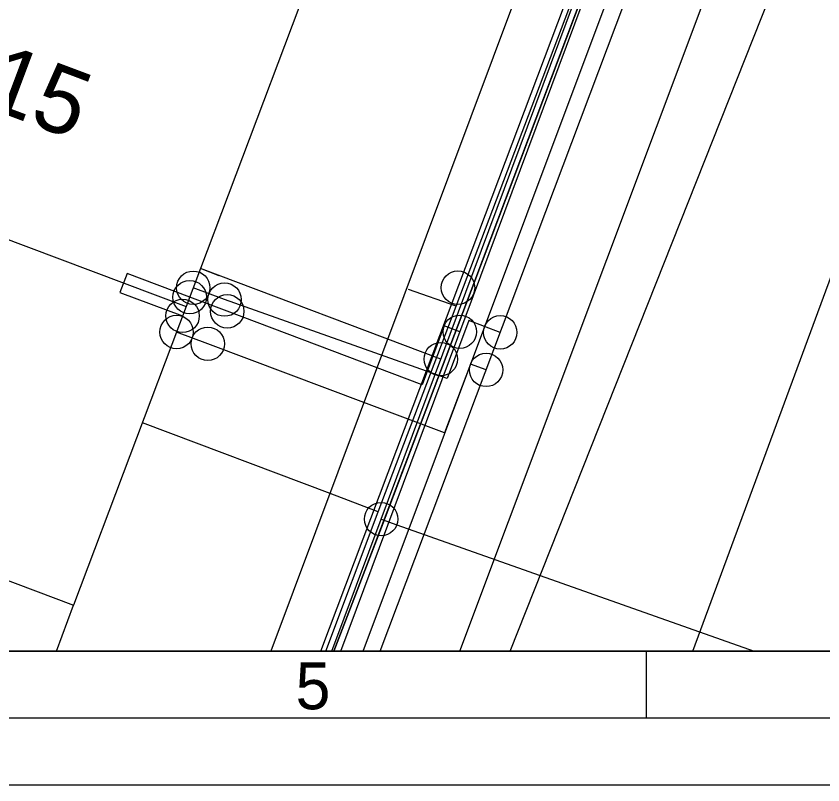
# Model space of a CAD drawing. Extents: x 192672 to 192910, y 446344 to 446512.
# Drawn here: x 192711.22 to 192723.28, y 446343.56 to 446355.04 of the extents above; entities that cross this region are included whole.
import ezdxf

# ---------------------------------------------------------------- set-up
doc = ezdxf.new("R2010")
doc.units = 0
for name, color, linetype in [('1010 viewport', 7, 'Continuous'), ('B-OI-KL-()_MANTELBUIS_WATER-G', 7, 'Continuous'), ('B-OI-KL-()_PUNTVANLEVERING_WATER-S', 7, 'Continuous'), ('B-OI-KL-BUISLEIDING_OLIEGASCHEMICALIEN_GASLAGEDRUK-G', 7, 'Continuous'), ('B-OI-KL-DATA-G', 7, 'Continuous'), ('B-OI-KL-DATA_KABELBED-G', 7, 'Continuous'), ('B-OI-KL-DATA_MOF-S', 7, 'Continuous'), ('B-OI-KL-ET_LS-G', 7, 'Continuous'), ('B-OI-KL-ET_LS_DELIVERYPOINT-S', 7, 'Continuous'), ('B-OI-KL-ET_LS_MOF-S', 7, 'Continuous'), ('B-OI-KL-GAS_LD_AFTAKZADEL-S', 7, 'Continuous'), ('B-OI-KL-GAS_LD_DELIVERYPOINT-S', 7, 'Continuous'), ('B-OI-KL-GAS_LD_OVERGANGSSTUK-S', 7, 'Continuous'), ('B-OI-KL-WATER-G', 7, 'Continuous'), ('B-OI-RI-RIOOLVRIJVERVAL-G', 7, 'Continuous'), ('Default', 7, 'Continuous'), ('huisnummerreeks BGT', 7, 'Continuous'), ('kant open verharding', 7, 'Continuous'), ('kant verharding', 7, 'Continuous'), ('pand op maaiveld vlak', 7, 'Continuous'), ('X-XX-AL-TEKENBLAD-S', 7, 'Continuous')]:
    doc.layers.add(name, color=color, linetype=linetype)

# ---------------------------------------------------------------- blocks, each defined once
blk = doc.blocks.new('B-OI-KL-GAS_LD_AFTAKZADEL-S')
at = {"layer": 'Default'}
blk.add_circle((0, 0), 0.25, dxfattribs=at)
blk = doc.blocks.new('B-OI-KL-GAS_LD_DELIVERYPOINT-S')
at = {"layer": 'Default'}
blk.add_circle((0, 0), 0.25, dxfattribs=at)
blk = doc.blocks.new('B-OI-KL-GAS_LD_OVERGANGSSTUK-S')
at = {"layer": 'Default'}
blk.add_circle((0, 0), 0.25, dxfattribs=at)
blk = doc.blocks.new('B-OI-KL-ET_LS_DELIVERYPOINT-S')
at = {"layer": 'Default'}
blk.add_circle((0, 0), 0.25, dxfattribs=at)
blk = doc.blocks.new('B-OI-KL-ET_LS_MOF-S')
at = {"layer": 'Default'}
blk.add_circle((0, 0), 0.25, dxfattribs=at)
blk = doc.blocks.new('B-OI-KL-()_PUNTVANLEVERING_WATER-S')
at = {"layer": 'Default'}
blk.add_circle((0, 0), 0.25, dxfattribs=at)
blk = doc.blocks.new('B-OI-KL-DATA_MOF-S')
at = {"layer": 'Default'}
blk.add_circle((0, 0), 0.25, dxfattribs=at)

msp = doc.modelspace()

# ---------------------------------------------------------------- linework, layer by layer
at = {"layer": '1010 viewport'}
msp.add_lwpolyline([(192675.743, 446509.756), (192860.643, 446509.756), (192860.643, 446345.556), (192675.743, 446345.556)], close=True, dxfattribs=at)
at = {"layer": 'B-OI-KL-()_MANTELBUIS_WATER-G'}
msp.add_lwpolyline([(192714.258, 446351.164), (192713.977, 446351.27)], dxfattribs=at)
at = {"layer": 'B-OI-KL-BUISLEIDING_OLIEGASCHEMICALIEN_GASLAGEDRUK-G'}
for points in [[(192716.663, 446345.556), (192724.878, 446367.369), (192730.944, 446383.739), (192732.424, 446387.662), (192733.825, 446391.479)], [(192714.338, 446350.807), (192713.87, 446350.984)], [(192718.456, 446350.317), (192717.989, 446350.496), (192717.663, 446349.63), (192714.338, 446350.807)], [(192714.087, 446350.146), (192713.621, 446350.322)], [(192718.245, 446349.756), (192718.011, 446349.844), (192717.623, 446348.814), (192714.087, 446350.146)]]:
    msp.add_lwpolyline(points, dxfattribs=at)
at = {"layer": 'B-OI-KL-DATA-G'}
msp.add_line((192715.85, 446345.556), (192716.633, 446347.634), dxfattribs=at)
for points in [[(192768.74, 446486.807), (192749.794, 446435.599), (192742.072, 446415.039), (192739.06, 446406.841), (192738.917, 446406.249), (192738.75, 446405.758), (192738.438, 446405.088), (192738.002, 446404.406), (192737.543, 446403.858), (192737.067, 446403.408), (192736.56, 446403.025), (192736.06, 446402.723), (192733.684, 446396.245), (192734.518, 446394.712), (192730.316, 446383.423), (192727.316, 446375.697), (192722.899, 446364.033), (192722.458, 446362.715), (192718.077, 446351.086), (192716.68, 446347.404), (192715.968, 446345.556)], [(192768.74, 446486.807), (192749.794, 446435.599), (192742.072, 446415.039), (192739.06, 446406.841), (192738.917, 446406.249), (192738.75, 446405.758), (192738.438, 446405.088), (192738.002, 446404.406), (192737.543, 446403.858), (192737.067, 446403.408), (192736.56, 446403.025), (192736.06, 446402.723), (192733.684, 446396.245), (192734.518, 446394.712), (192730.316, 446383.423), (192727.316, 446375.697), (192722.899, 446364.033), (192722.458, 446362.715), (192718.077, 446351.086), (192716.68, 446347.404), (192715.968, 446345.556)], [(192768.74, 446486.807), (192749.794, 446435.599), (192742.072, 446415.039), (192739.06, 446406.841), (192738.917, 446406.249), (192738.75, 446405.758), (192738.438, 446405.088), (192738.002, 446404.406), (192737.543, 446403.858), (192737.067, 446403.408), (192736.56, 446403.025), (192736.06, 446402.723), (192733.684, 446396.245), (192734.518, 446394.712), (192730.316, 446383.423), (192727.316, 446375.697), (192722.899, 446364.033), (192722.458, 446362.715), (192718.077, 446351.086), (192716.68, 446347.404), (192715.968, 446345.556)], [(192768.74, 446486.807), (192749.794, 446435.599), (192742.072, 446415.039), (192739.06, 446406.841), (192738.917, 446406.249), (192738.75, 446405.758), (192738.438, 446405.088), (192738.002, 446404.406), (192737.543, 446403.858), (192737.067, 446403.408), (192736.56, 446403.025), (192736.06, 446402.723), (192733.684, 446396.245), (192734.518, 446394.712), (192730.316, 446383.423), (192727.316, 446375.697), (192722.899, 446364.033), (192722.458, 446362.715), (192718.077, 446351.086), (192716.68, 446347.404), (192715.968, 446345.556)], [(192768.74, 446486.807), (192749.794, 446435.599), (192742.072, 446415.039), (192739.06, 446406.841), (192738.917, 446406.249), (192738.75, 446405.758), (192738.438, 446405.088), (192738.002, 446404.406), (192737.543, 446403.858), (192737.067, 446403.408), (192736.56, 446403.025), (192736.06, 446402.723), (192733.684, 446396.245), (192734.518, 446394.712), (192730.316, 446383.423), (192727.316, 446375.697), (192722.899, 446364.033), (192722.458, 446362.715), (192718.077, 446351.086), (192716.68, 446347.404), (192715.968, 446345.556)], [(192768.74, 446486.807), (192749.794, 446435.599), (192742.072, 446415.039), (192739.06, 446406.841), (192738.917, 446406.249), (192738.75, 446405.758), (192738.438, 446405.088), (192738.002, 446404.406), (192737.543, 446403.858), (192737.067, 446403.408), (192736.56, 446403.025), (192736.06, 446402.723), (192733.684, 446396.245), (192734.518, 446394.712), (192730.316, 446383.423), (192727.316, 446375.697), (192722.899, 446364.033), (192722.458, 446362.715), (192718.077, 446351.086), (192716.68, 446347.404), (192715.968, 446345.556)], [(192768.74, 446486.807), (192749.794, 446435.599), (192742.072, 446415.039), (192739.06, 446406.841), (192738.917, 446406.249), (192738.75, 446405.758), (192738.438, 446405.088), (192738.002, 446404.406), (192737.543, 446403.858), (192737.067, 446403.408), (192736.56, 446403.025), (192736.06, 446402.723), (192733.684, 446396.245), (192734.518, 446394.712), (192730.316, 446383.423), (192727.316, 446375.697), (192722.899, 446364.033), (192722.458, 446362.715), (192718.077, 446351.086), (192716.68, 446347.404), (192715.968, 446345.556)], [(192768.74, 446486.807), (192749.794, 446435.599), (192742.072, 446415.039), (192739.06, 446406.841), (192738.917, 446406.249), (192738.75, 446405.758), (192738.438, 446405.088), (192738.002, 446404.406), (192737.543, 446403.858), (192737.067, 446403.408), (192736.56, 446403.025), (192736.06, 446402.723), (192733.684, 446396.245), (192734.518, 446394.712), (192730.316, 446383.423), (192727.316, 446375.697), (192722.899, 446364.033), (192722.458, 446362.715), (192718.077, 446351.086), (192716.68, 446347.404), (192715.968, 446345.556)], [(192768.74, 446486.807), (192749.794, 446435.599), (192742.072, 446415.039), (192739.06, 446406.841), (192738.917, 446406.249), (192738.75, 446405.758), (192738.438, 446405.088), (192738.002, 446404.406), (192737.543, 446403.858), (192737.067, 446403.408), (192736.56, 446403.025), (192736.06, 446402.723), (192733.684, 446396.245), (192734.518, 446394.712), (192730.316, 446383.423), (192727.316, 446375.697), (192722.899, 446364.033), (192722.458, 446362.715), (192718.077, 446351.086), (192716.68, 446347.404), (192715.968, 446345.556)], [(192768.74, 446486.807), (192749.794, 446435.599), (192742.072, 446415.039), (192739.06, 446406.841), (192738.917, 446406.249), (192738.75, 446405.758), (192738.438, 446405.088), (192738.002, 446404.406), (192737.543, 446403.858), (192737.067, 446403.408), (192736.56, 446403.025), (192736.06, 446402.723), (192733.684, 446396.245), (192734.518, 446394.712), (192730.316, 446383.423), (192727.316, 446375.697), (192722.899, 446364.033), (192722.458, 446362.715), (192718.077, 446351.086), (192716.68, 446347.404), (192715.968, 446345.556)], [(192768.74, 446486.807), (192749.794, 446435.599), (192742.072, 446415.039), (192739.06, 446406.841), (192738.917, 446406.249), (192738.75, 446405.758), (192738.438, 446405.088), (192738.002, 446404.406), (192737.543, 446403.858), (192737.067, 446403.408), (192736.56, 446403.025), (192736.06, 446402.723), (192733.684, 446396.245), (192734.518, 446394.712), (192730.316, 446383.423), (192727.316, 446375.697), (192722.899, 446364.033), (192722.458, 446362.715), (192718.077, 446351.086), (192716.68, 446347.404), (192715.968, 446345.556)], [(192768.74, 446486.807), (192749.794, 446435.599), (192742.072, 446415.039), (192739.06, 446406.841), (192738.917, 446406.249), (192738.75, 446405.758), (192738.438, 446405.088), (192738.002, 446404.406), (192737.543, 446403.858), (192737.067, 446403.408), (192736.56, 446403.025), (192736.06, 446402.723), (192733.684, 446396.245), (192734.518, 446394.712), (192730.316, 446383.423), (192727.316, 446375.697), (192722.899, 446364.033), (192722.458, 446362.715), (192718.077, 446351.086), (192716.68, 446347.404), (192715.968, 446345.556)], [(192768.74, 446486.807), (192749.794, 446435.599), (192742.072, 446415.039), (192739.06, 446406.841), (192738.917, 446406.249), (192738.75, 446405.758), (192738.438, 446405.088), (192738.002, 446404.406), (192737.543, 446403.858), (192737.067, 446403.408), (192736.56, 446403.025), (192736.06, 446402.723), (192733.684, 446396.245), (192734.518, 446394.712), (192730.316, 446383.423), (192727.316, 446375.697), (192722.899, 446364.033), (192722.458, 446362.715), (192718.077, 446351.086), (192716.68, 446347.404), (192715.968, 446345.556)], [(192768.74, 446486.807), (192749.794, 446435.599), (192742.072, 446415.039), (192739.06, 446406.841), (192738.917, 446406.249), (192738.75, 446405.758), (192738.438, 446405.088), (192738.002, 446404.406), (192737.543, 446403.858), (192737.067, 446403.408), (192736.56, 446403.025), (192736.06, 446402.723), (192733.684, 446396.245), (192734.518, 446394.712), (192730.316, 446383.423), (192727.316, 446375.697), (192722.899, 446364.033), (192722.458, 446362.715), (192718.077, 446351.086), (192716.68, 446347.404), (192715.968, 446345.556)], [(192768.74, 446486.807), (192749.794, 446435.599), (192742.072, 446415.039), (192739.06, 446406.841), (192738.917, 446406.249), (192738.75, 446405.758), (192738.438, 446405.088), (192738.002, 446404.406), (192737.543, 446403.858), (192737.067, 446403.408), (192736.56, 446403.025), (192736.06, 446402.723), (192733.684, 446396.245), (192734.518, 446394.712), (192730.316, 446383.423), (192727.316, 446375.697), (192722.899, 446364.033), (192722.458, 446362.715), (192718.077, 446351.086), (192716.68, 446347.404), (192715.968, 446345.556)], [(192675.743, 446430.156), (192678.122, 446429.261), (192683.193, 446427.673), (192696.077, 446422.823), (192719.012, 446414.118), (192720.2, 446413.77), (192739.06, 446406.841), (192738.917, 446406.249), (192738.75, 446405.758), (192738.438, 446405.088), (192738.002, 446404.406), (192737.543, 446403.858), (192737.067, 446403.408), (192736.56, 446403.025), (192736.06, 446402.723), (192733.684, 446396.245), (192734.518, 446394.712), (192730.316, 446383.423), (192727.316, 446375.697), (192722.899, 446364.033), (192722.458, 446362.715), (192718.077, 446351.086), (192716.68, 446347.404), (192715.968, 446345.556)], [(192675.743, 446430.156), (192678.122, 446429.261), (192683.193, 446427.673), (192696.077, 446422.823), (192719.012, 446414.118), (192720.2, 446413.77), (192739.06, 446406.841), (192738.917, 446406.249), (192738.75, 446405.758), (192738.438, 446405.088), (192738.002, 446404.406), (192737.543, 446403.858), (192737.067, 446403.408), (192736.56, 446403.025), (192736.06, 446402.723), (192733.684, 446396.245), (192734.518, 446394.712), (192730.316, 446383.423), (192727.316, 446375.697), (192722.899, 446364.033), (192722.458, 446362.715), (192718.077, 446351.086), (192716.68, 446347.404), (192715.968, 446345.556)], [(192675.743, 446430.156), (192678.122, 446429.261), (192683.193, 446427.673), (192696.077, 446422.823), (192719.012, 446414.118), (192720.2, 446413.77), (192739.06, 446406.841), (192738.917, 446406.249), (192738.75, 446405.758), (192738.438, 446405.088), (192738.002, 446404.406), (192737.543, 446403.858), (192737.067, 446403.408), (192736.56, 446403.025), (192736.06, 446402.723), (192733.684, 446396.245), (192734.518, 446394.712), (192730.316, 446383.423), (192727.316, 446375.697), (192722.899, 446364.033), (192722.458, 446362.715), (192718.077, 446351.086), (192716.68, 446347.404), (192715.968, 446345.556)], [(192675.743, 446430.156), (192678.122, 446429.261), (192683.193, 446427.673), (192696.077, 446422.823), (192719.012, 446414.118), (192720.2, 446413.77), (192739.06, 446406.841), (192738.917, 446406.249), (192738.75, 446405.758), (192738.438, 446405.088), (192738.002, 446404.406), (192737.543, 446403.858), (192737.067, 446403.408), (192736.56, 446403.025), (192736.06, 446402.723), (192733.684, 446396.245), (192734.518, 446394.712), (192730.316, 446383.423), (192727.316, 446375.697), (192722.899, 446364.033), (192722.458, 446362.715), (192718.077, 446351.086), (192716.68, 446347.404), (192715.968, 446345.556)], [(192675.743, 446430.156), (192678.122, 446429.261), (192683.193, 446427.673), (192696.077, 446422.823), (192719.012, 446414.118), (192720.2, 446413.77), (192739.06, 446406.841), (192738.917, 446406.249), (192738.75, 446405.758), (192738.438, 446405.088), (192738.002, 446404.406), (192737.543, 446403.858), (192737.067, 446403.408), (192736.56, 446403.025), (192736.06, 446402.723), (192733.684, 446396.245), (192734.518, 446394.712), (192730.316, 446383.423), (192727.316, 446375.697), (192722.899, 446364.033), (192722.458, 446362.715), (192718.077, 446351.086), (192716.68, 446347.404), (192715.968, 446345.556)], [(192675.743, 446430.156), (192678.122, 446429.261), (192683.193, 446427.673), (192696.077, 446422.823), (192719.012, 446414.118), (192720.2, 446413.77), (192739.06, 446406.841), (192738.917, 446406.249), (192738.75, 446405.758), (192738.438, 446405.088), (192738.002, 446404.406), (192737.543, 446403.858), (192737.067, 446403.408), (192736.56, 446403.025), (192736.06, 446402.723), (192733.684, 446396.245), (192734.518, 446394.712), (192730.316, 446383.423), (192727.316, 446375.697), (192722.899, 446364.033), (192722.458, 446362.715), (192718.077, 446351.086), (192716.68, 446347.404), (192715.968, 446345.556)], [(192715.968, 446345.556), (192716.68, 446347.404), (192718.077, 446351.086), (192722.458, 446362.715), (192722.899, 446364.033), (192727.316, 446375.697), (192730.316, 446383.423), (192734.518, 446394.712), (192733.684, 446396.245), (192736.06, 446402.723), (192736.56, 446403.025), (192737.067, 446403.408), (192737.543, 446403.858), (192738.002, 446404.406), (192738.438, 446405.088), (192738.75, 446405.758), (192738.917, 446406.249), (192739.06, 446406.841), (192720.2, 446413.77), (192719.012, 446414.118), (192698.154, 446422.035)], [(192715.968, 446345.556), (192716.68, 446347.404), (192718.077, 446351.086), (192722.458, 446362.715), (192722.899, 446364.033), (192727.316, 446375.697), (192730.316, 446383.423), (192734.518, 446394.712), (192733.684, 446396.245), (192736.06, 446402.723), (192736.56, 446403.025), (192737.067, 446403.408), (192737.543, 446403.858), (192738.002, 446404.406), (192738.438, 446405.088), (192738.75, 446405.758), (192738.917, 446406.249), (192739.06, 446406.841), (192720.2, 446413.77), (192719.012, 446414.118), (192703.056, 446420.174)], [(192715.968, 446345.556), (192716.68, 446347.404), (192718.077, 446351.086), (192722.458, 446362.715), (192722.899, 446364.033), (192727.316, 446375.697), (192730.316, 446383.423), (192734.518, 446394.712), (192733.684, 446396.245), (192736.06, 446402.723), (192736.56, 446403.025), (192737.067, 446403.408), (192737.543, 446403.858), (192738.002, 446404.406), (192738.438, 446405.088), (192738.75, 446405.758), (192738.917, 446406.249), (192739.06, 446406.841), (192720.2, 446413.77), (192719.012, 446414.118), (192707.704, 446418.41)], [(192733.785, 446392.743), (192730.316, 446383.423), (192727.316, 446375.697), (192722.899, 446364.033), (192722.458, 446362.715), (192718.077, 446351.086), (192716.68, 446347.404), (192715.968, 446345.556)], [(192718.113, 446380.217), (192718.126, 446380.244), (192727.316, 446375.697), (192722.899, 446364.033), (192722.458, 446362.715), (192718.077, 446351.086), (192716.68, 446347.404), (192715.968, 446345.556)], [(192718.113, 446380.217), (192718.126, 446380.244), (192727.316, 446375.697), (192722.899, 446364.033), (192722.458, 446362.715), (192718.077, 446351.086), (192716.68, 446347.404), (192715.968, 446345.556)], [(192718.113, 446380.217), (192718.126, 446380.244), (192727.316, 446375.697), (192722.899, 446364.033), (192722.458, 446362.715), (192718.077, 446351.086), (192716.68, 446347.404), (192715.968, 446345.556)], [(192718.113, 446380.217), (192718.126, 446380.244), (192727.316, 446375.697), (192722.899, 446364.033), (192722.458, 446362.715), (192718.077, 446351.086), (192716.68, 446347.404), (192715.968, 446345.556)], [(192718.113, 446380.217), (192718.126, 446380.244), (192727.316, 446375.697), (192722.899, 446364.033), (192722.458, 446362.715), (192718.077, 446351.086), (192716.68, 446347.404), (192715.968, 446345.556)], [(192718.113, 446380.217), (192718.126, 446380.244), (192727.316, 446375.697), (192722.899, 446364.033), (192722.458, 446362.715), (192718.077, 446351.086), (192716.68, 446347.404), (192715.968, 446345.556)], [(192718.113, 446380.217), (192718.126, 446380.244), (192727.316, 446375.697), (192722.899, 446364.033), (192722.458, 446362.715), (192718.077, 446351.086), (192716.68, 446347.404), (192715.968, 446345.556)], [(192718.113, 446380.217), (192718.126, 446380.244), (192727.316, 446375.697), (192722.899, 446364.033), (192722.458, 446362.715), (192718.077, 446351.086), (192716.68, 446347.404), (192716.398, 446346.672)], [(192718.113, 446380.217), (192718.126, 446380.244), (192727.316, 446375.697), (192722.899, 446364.033), (192722.458, 446362.715), (192718.202, 446351.418)], [(192717.8, 446350.711), (192719.809, 446356.02)], [(192717.8, 446350.711), (192717.084, 446350.956)], [(192716.633, 446347.634), (192717.8, 446350.711)], [(192716.633, 446347.634), (192715.917, 446347.909), (192713.11, 446348.966)]]:
    msp.add_lwpolyline(points, dxfattribs=at)
at = {"layer": 'B-OI-KL-DATA_KABELBED-G'}
msp.add_line((192716.398, 446346.672), (192715.968, 446345.556), dxfattribs=at)
for points in [[(192715.778, 446345.556), (192717.157, 446349.216), (192720.197, 446357.284), (192722.27, 446362.784), (192722.711, 446364.103), (192724.092, 446367.75), (192725.922, 446372.585), (192725.924, 446372.588), (192726.95, 446375.299), (192730.073, 446383.511), (192734.61, 446395.441)], [(192720.004, 446356.201), (192718.202, 446351.418)], [(192718.202, 446351.418), (192716.398, 446346.672)]]:
    msp.add_lwpolyline(points, dxfattribs=at)
at = {"layer": 'B-OI-KL-ET_LS-G'}
for points in [[(192716.073, 446345.556), (192727.138, 446375.229), (192730.971, 446383.179), (192732.504, 446387.295), (192732.765, 446387.575)], [(192713.817, 446350.843), (192712.881, 446351.196), (192712.775, 446350.915), (192713.711, 446350.563)], [(192714.378, 446350.632), (192713.817, 446350.843)], [(192717.852, 446350.326), (192717.618, 446350.413), (192717.29, 446349.535), (192714.378, 446350.632)]]:
    msp.add_lwpolyline(points, dxfattribs=at)
at = {"layer": 'B-OI-KL-WATER-G'}
for points in [[(192715.942, 446345.556), (192716.677, 446347.527), (192733.49, 446392.627), (192735.123, 446396.62)], [(192717.568, 446349.917), (192713.977, 446351.27)], [(192716.677, 446347.527), (192716.911, 446347.44), (192722.25, 446345.556)]]:
    msp.add_lwpolyline(points, dxfattribs=at)
at = {"layer": 'B-OI-RI-RIOOLVRIJVERVAL-G'}
for p, q in [((192718.603, 446345.556), (192727.764, 446368.64)), ((192721.331, 446345.556), (192725.88, 446357.88))]:
    msp.add_line(p, q, dxfattribs=at)
at = {"layer": 'kant open verharding'}
msp.add_line((192722.057, 446364.352), (192715.03, 446345.556), dxfattribs=at)
at = {"layer": 'kant verharding'}
for p, q in [((192716.41, 446345.556), (192721.66, 446359.568)), ((192717.853, 446345.556), (192723.089, 446359.513))]:
    msp.add_line(p, q, dxfattribs=at)
at = {"layer": 'pand op maaiveld vlak'}
for p, q in [((192715.445, 446355.165), (192713.764, 446350.703)), ((192702.572, 446354.92), (192713.764, 446350.703)), ((192713.764, 446350.703), (192712.083, 446346.24)), ((192700.89, 446350.458), (192712.083, 446346.24)), ((192711.825, 446345.556), (192712.083, 446346.24))]:
    msp.add_line(p, q, dxfattribs=at)
at = {"layer": 'X-XX-AL-TEKENBLAD-S'}
for p, q in [((192720.643, 446344.556), (192720.643, 446345.556)), ((192674.743, 446344.556), (192908.543, 446344.556)), ((192671.743, 446343.556), (192909.543, 446343.556))]:
    msp.add_line(p, q, dxfattribs=at)
msp.add_lwpolyline([(192675.743, 446345.556), (192907.543, 446345.556), (192907.543, 446509.756), (192675.743, 446509.756)], close=True, dxfattribs=at)

# ---------------------------------------------------------------- block references
at = {"layer": 'B-OI-KL-()_PUNTVANLEVERING_WATER-S'}
for p in [(192717.568, 446349.917), (192716.677, 446347.527)]:
    msp.add_blockref('B-OI-KL-()_PUNTVANLEVERING_WATER-S', p, dxfattribs=at)
at = {"layer": 'B-OI-KL-DATA_MOF-S'}
msp.add_blockref('B-OI-KL-DATA_MOF-S', (192717.824, 446350.985), dxfattribs=at)
at = {"layer": 'B-OI-KL-ET_LS_DELIVERYPOINT-S'}
for p in [(192713.817, 446350.843), (192713.711, 446350.563)]:
    msp.add_blockref('B-OI-KL-ET_LS_DELIVERYPOINT-S', p, dxfattribs=at)
at = {"layer": 'B-OI-KL-ET_LS_MOF-S'}
for p in [(192714.378, 446350.632), (192717.852, 446350.326)]:
    msp.add_blockref('B-OI-KL-ET_LS_MOF-S', p, dxfattribs=at)
at = {"layer": 'B-OI-KL-GAS_LD_AFTAKZADEL-S'}
for p in [(192718.456, 446350.317), (192718.245, 446349.756)]:
    msp.add_blockref('B-OI-KL-GAS_LD_AFTAKZADEL-S', p, dxfattribs=at)
at = {"layer": 'B-OI-KL-GAS_LD_DELIVERYPOINT-S'}
for p in [(192713.87, 446350.984), (192713.621, 446350.322)]:
    msp.add_blockref('B-OI-KL-GAS_LD_DELIVERYPOINT-S', p, dxfattribs=at)
at = {"layer": 'B-OI-KL-GAS_LD_OVERGANGSSTUK-S'}
for p in [(192714.338, 446350.807), (192714.087, 446350.146)]:
    msp.add_blockref('B-OI-KL-GAS_LD_OVERGANGSSTUK-S', p, dxfattribs=at)

# ---------------------------------------------------------------- texts
at = {"layer": 'huisnummerreeks BGT'}
msp.add_text('115', height=1, rotation=339.4, dxfattribs=at).set_placement((192709.999, 446353.974))
at = {"layer": 'X-XX-AL-TEKENBLAD-S'}
msp.add_text('5', height=0.7, dxfattribs=at).set_placement((192715.399, 446344.685))

doc.saveas('drawing.dxf')
